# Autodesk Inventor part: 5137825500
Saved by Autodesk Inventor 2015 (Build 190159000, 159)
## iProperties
Created: 2020-07
Part Number: 5137825500
Checked By: TraceParts S.A.
Material: Generic
Catalog Web Link: www.traceparts.com
Document SubType Name: Modeling
Designer: TraceParts
Density: 1 g/cm^3
Appearance: Default
Company: TraceParts S.A.
Author: TraceParts
REFERENCE: 5137825500
DESIGN: CVAB/4-2000/315 N D 0,17KW (230V) 50Hz - 5137825500
SUPPLIER: Soler & Palau
TraceParts.PartNumber: 10-14122018-105188
TraceParts.PartTitle: CVAT-N
TraceParts.InstanceId: 10-14122018-10518879NLUKODA1OB3PLMGFBNN56EG
TraceParts.PartStatus: Published
TraceParts.PartVersion: 1.0.4
TRACEPARTS: TRACEPARTS
TraceParts.PartLanguage: en
TraceParts.ClassPath: SOLER_PALAU:10-14122018-105188
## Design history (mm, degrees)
feature "5137825500"
body "Solid1"
